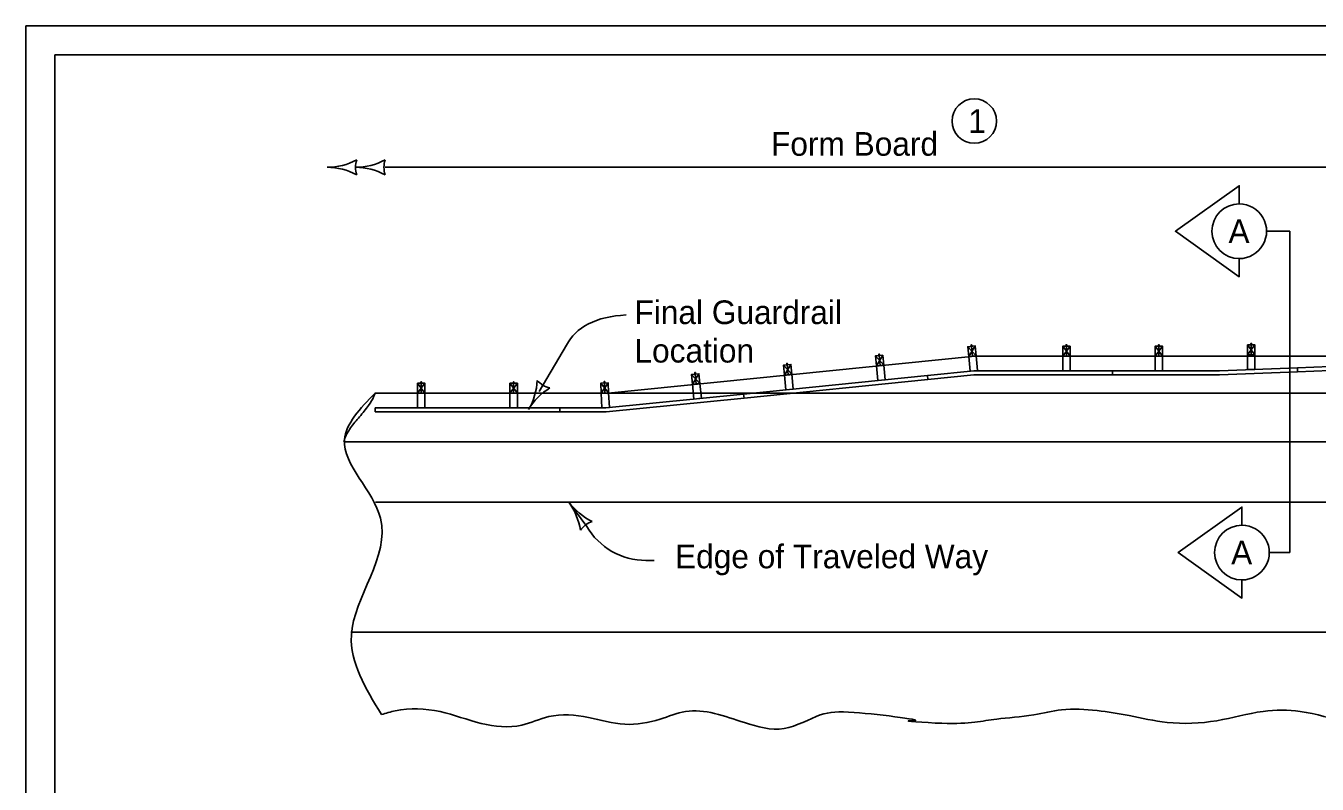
# Model space of a CAD drawing. Extents: x 10133 to 81668, y 5848 to 11018.
# Drawn here: x 10133 to 11006, y 9431 to 9944 of the extents above; entities that cross this region are included whole.
import ezdxf

# ---------------------------------------------------------------- set-up
doc = ezdxf.new("R2010")
doc.units = 0
for name, color, linetype in [('dsnStdLabel', 7, 'Continuous'), ('dsnStdLineWork', 7, 'Continuous'), ('dsnStdNote', 7, 'Continuous'), ('dsnStdPattern', 7, 'Continuous'), ('dsnStdSection', 7, 'Continuous'), ('dsnStdShading', 7, 'Continuous'), ('SheetBorder', 7, 'Continuous'), ('ShtPlotShape', 7, 'Continuous'), ('ShtPlotShapeBatchPrint', 7, 'Continuous')]:
    doc.layers.add(name, color=color, linetype=linetype)

msp = doc.modelspace()

# ---------------------------------------------------------------- linework, layer by layer
at = {"layer": 'dsnStdLabel'}
msp.add_circle((10773.85, 9879.62), 15, dxfattribs=at)
at = {"layer": 'dsnStdLineWork'}
for p, q in [((11403.96, 9729.27), (10992.39, 9712.81)), ((10526.39, 9695.63), (10774.18, 9720.71)), ((11022.02, 9720.71), (10774.18, 9720.71)), ((11404.06, 9726.57), (10992.39, 9710.1)), ((10992.39, 9712.81), (10939.63, 9710.7)), ((10992.5, 9710.11), (10939.65, 9707.99)), ((10992.39, 9712.81), (10992.5, 9710.11)), ((10992.39, 9712.81), (10992.5, 9710.11)), ((10368.64, 9695.63), (10526.39, 9695.63)), ((10368.64, 9695.63), (11500.75, 9695.63)), ((10347.65, 9662.65), (11995.12, 9662.65)), ((11500.75, 9662.65), (10347.65, 9662.65)), ((10368.86, 9622), (11982.65, 9622))]:
    msp.add_line(p, q, dxfattribs=at)
for points in [[(10368.64, 9695.63), (10347.99, 9664.08), (10372.36, 9611), (10352.66, 9531.9), (10372.93, 9478.29)], [(10347.65, 9662.65), (10347.99, 9664.08), (10349.68, 9668.15), (10352.09, 9672.07), (10358.15, 9679.69), (10364.3, 9687.38), (10367.83, 9693.49), (10368.64, 9695.63)], [(10372.93, 9478.29), (10382.36, 9480.86), (10412.58, 9480.29), (10440.52, 9472.31), (10467.89, 9471.16), (10486.14, 9476.87), (10512.94, 9476.3), (10537.46, 9471.74), (10561.41, 9475.16), (10578.52, 9480.29), (10618.43, 9472.88), (10645.23, 9468.88), (10669.75, 9478.01), (10692.56, 9479.72), (10731.34, 9474.02), (10730.77, 9474.02), (10751.92, 9472.41), (10788.99, 9475.27), (10814.08, 9478.12), (10832.9, 9481.54), (10856.85, 9480.97), (10878.51, 9477.55), (10904.17, 9472.98), (10937.82, 9474.13), (10969.18, 9480.4), (10994.27, 9480.4), (11026.2, 9472.98), (11055.29, 9470.13), (11088.93, 9476.98), (11121.43, 9480.4), (11155.65, 9473.55), (11181.31, 9470.7), (11203.54, 9474.13), (11231.49, 9489.53), (11241.75, 9491.81), (11266.27, 9494.09), (11296.93, 9494.66), (11318.03, 9494.66), (11371.34, 9485.38)]]:
    msp.add_spline(points, degree=3, dxfattribs=at)
at = {"layer": 'dsnStdNote'}
for p, q in [((10774.47, 9727.54), (10770.15, 9720.41)), ((10771.88, 9728.26), (10771.87, 9728.33)), ((10833.64, 9727.37), (10838.64, 9720.71)), ((10838.64, 9727.37), (10833.64, 9720.71)), ((10836.14, 9728.35), (10836.14, 9728.42)), ((10836.14, 9720.71), (10836.14, 9727.37)), ((10896.14, 9727.37), (10901.14, 9720.71)), ((10901.14, 9727.37), (10896.14, 9720.71)), ((10898.64, 9728.35), (10898.64, 9728.42)), ((10898.64, 9720.71), (10898.64, 9727.37)), ((10958.64, 9728.24), (10963.64, 9721.57)), ((10963.64, 9728.24), (10958.64, 9721.57)), ((10961.14, 9729.21), (10961.14, 9729.28)), ((10961.14, 9721.57), (10961.14, 9728.24)), ((10707.03, 9720.76), (10712.67, 9714.63)), ((10712, 9721.26), (10707.69, 9714.13)), ((10709.42, 9721.98), (10709.41, 9722.05)), ((10710.18, 9714.38), (10709.51, 9721.01)), ((10769.49, 9727.04), (10775.13, 9720.91)), ((10770.15, 9720.41), (10775.13, 9720.91)), ((10772.64, 9720.66), (10770.15, 9720.41)), ((10772.64, 9720.66), (10770.15, 9720.41)), ((10771.15, 9710.45), (10770.15, 9720.41)), ((10772.64, 9720.66), (10771.98, 9727.29)), ((10775.13, 9720.91), (10776.13, 9710.95)), ((10833.64, 9720.71), (10838.64, 9720.71)), ((10833.64, 9710.7), (10833.64, 9720.71)), ((10838.64, 9720.71), (10838.64, 9710.7)), ((10896.14, 9720.71), (10901.14, 9720.71)), ((10896.14, 9710.7), (10896.14, 9720.71)), ((10901.14, 9720.71), (10901.14, 9710.7)), ((10958.64, 9721.57), (10963.64, 9721.57)), ((10958.64, 9711.56), (10958.64, 9721.57)), ((10963.64, 9721.57), (10963.64, 9711.56)), ((10644.84, 9714.51), (10650.48, 9708.38)), ((10649.81, 9715.01), (10645.51, 9707.88)), ((10647.23, 9715.73), (10647.22, 9715.8)), ((10647.99, 9708.13), (10647.33, 9714.76)), ((10707.69, 9714.13), (10712.67, 9714.63)), ((10708.69, 9704.17), (10707.69, 9714.13)), ((10712.67, 9714.63), (10713.67, 9704.67)), ((10773.64, 9710.7), (10742.28, 9707.55)), ((10776.13, 9710.95), (10771.15, 9710.45)), ((10773.64, 9710.7), (10867.39, 9710.7)), ((10838.64, 9710.7), (10833.64, 9710.7)), ((10867.39, 9707.99), (10867.39, 9710.7)), ((10867.39, 9710.7), (10939.63, 9710.7)), ((10867.39, 9707.99), (10867.39, 9710.7)), ((10901.14, 9710.7), (10896.14, 9710.7)), ((10963.64, 9711.56), (10958.64, 9711.56)), ((10397.39, 9702.3), (10402.39, 9695.63)), ((10402.39, 9702.3), (10397.39, 9695.63)), ((10399.89, 9703.27), (10399.89, 9703.34)), ((10399.89, 9695.63), (10399.89, 9702.3)), ((10459.89, 9702.3), (10464.89, 9695.63)), ((10464.89, 9702.3), (10459.89, 9695.63)), ((10462.39, 9703.27), (10462.39, 9703.34)), ((10462.39, 9695.63), (10462.39, 9702.3)), ((10521.28, 9702.36), (10526.61, 9695.92)), ((10526.28, 9702.61), (10521.62, 9695.67)), ((10523.73, 9703.46), (10523.73, 9703.53)), ((10524.11, 9695.8), (10523.78, 9702.49)), ((10582.66, 9708.3), (10588.3, 9702.13)), ((10587.64, 9708.8), (10583.33, 9701.63)), ((10583.33, 9701.63), (10588.3, 9702.13)), ((10584.32, 9691.63), (10583.33, 9701.63)), ((10585.05, 9709.52), (10585.05, 9709.59)), ((10585.81, 9701.88), (10585.15, 9708.55)), ((10588.3, 9702.13), (10589.3, 9692.13)), ((10617.9, 9695.05), (10742.28, 9707.55)), ((10618.17, 9692.35), (10742.55, 9704.85)), ((10645.51, 9707.88), (10650.49, 9708.38)), ((10646.51, 9697.92), (10645.51, 9707.88)), ((10650.49, 9708.38), (10651.49, 9698.42)), ((10713.67, 9704.67), (10708.69, 9704.17)), ((10742.55, 9704.85), (10742.28, 9707.55)), ((10742.55, 9704.87), (10742.28, 9707.55)), ((10773.64, 9707.99), (10742.55, 9704.87)), ((10773.64, 9707.99), (10867.39, 9707.99)), ((10867.39, 9707.99), (10939.65, 9707.99)), ((10397.39, 9695.63), (10402.4, 9695.63)), ((10397.39, 9685.63), (10397.39, 9695.63)), ((10402.4, 9695.63), (10402.4, 9685.63)), ((10459.89, 9695.63), (10464.9, 9695.63)), ((10459.89, 9685.63), (10459.89, 9695.63)), ((10464.9, 9695.63), (10464.9, 9685.63)), ((10521.62, 9695.67), (10526.61, 9695.92)), ((10522.11, 9685.63), (10521.62, 9695.67)), ((10524.62, 9685.63), (10617.9, 9695.05)), ((10526.61, 9695.92), (10527.11, 9685.88)), ((10618.17, 9692.34), (10617.9, 9695.05)), ((10618.17, 9692.35), (10617.9, 9695.05)), ((10651.49, 9698.42), (10646.51, 9697.92)), ((10368.64, 9685.63), (10493.64, 9685.63)), ((10368.64, 9682.92), (10368.64, 9685.63)), ((10402.4, 9685.63), (10397.39, 9685.63)), ((10464.9, 9685.63), (10459.89, 9685.63)), ((10493.64, 9685.63), (10524.62, 9685.63)), ((10493.64, 9682.92), (10493.64, 9685.63)), ((10527.11, 9685.88), (10522.11, 9685.63)), ((10524.89, 9682.92), (10618.17, 9692.34)), ((10589.3, 9692.13), (10584.32, 9691.63)), ((10368.64, 9682.92), (10493.64, 9682.92)), ((10493.64, 9682.92), (10524.89, 9682.92))]:
    msp.add_line(p, q, dxfattribs=at)
for points in [[(10770.15, 9720.41), (10775.13, 9720.91), (10774.47, 9727.54), (10769.49, 9727.04)], [(10833.64, 9720.71), (10838.64, 9720.71), (10838.64, 9727.37), (10833.64, 9727.37)], [(10896.14, 9720.71), (10901.14, 9720.71), (10901.14, 9727.37), (10896.14, 9727.37)], [(10958.64, 9721.57), (10963.64, 9721.57), (10963.64, 9728.24), (10958.64, 9728.24)], [(10707.69, 9714.13), (10712.67, 9714.63), (10712, 9721.26), (10707.03, 9720.76)], [(10645.51, 9707.88), (10650.48, 9708.38), (10649.81, 9715.01), (10644.84, 9714.51)], [(10397.39, 9695.63), (10402.39, 9695.63), (10402.39, 9702.3), (10397.39, 9702.3)], [(10459.89, 9695.63), (10464.89, 9695.63), (10464.89, 9702.3), (10459.89, 9702.3)], [(10521.62, 9695.67), (10526.61, 9695.92), (10526.28, 9702.61), (10521.28, 9702.36)], [(10583.33, 9701.63), (10588.3, 9702.13), (10587.64, 9708.8), (10582.66, 9708.3)]]:
    msp.add_lwpolyline(points, close=True, dxfattribs=at)
for points in [[(10771.65, 9727.26), (10771.6, 9727.69), (10772.27, 9727.75), (10772.31, 9727.32)], [(10771.74, 9727.7), (10771.69, 9728.24), (10772.08, 9728.28), (10772.13, 9727.74)], [(10835.8, 9727.37), (10835.8, 9727.81), (10836.47, 9727.81), (10836.47, 9727.37)], [(10835.94, 9727.81), (10835.94, 9728.35), (10836.33, 9728.35), (10836.33, 9727.81)], [(10898.31, 9727.37), (10898.31, 9727.81), (10898.97, 9727.81), (10898.97, 9727.37)], [(10898.45, 9727.81), (10898.45, 9728.35), (10898.83, 9728.35), (10898.83, 9727.81)], [(10960.81, 9728.24), (10960.81, 9728.67), (10961.47, 9728.67), (10961.47, 9728.24)], [(10960.95, 9728.67), (10960.95, 9729.21), (10961.33, 9729.21), (10961.33, 9728.67)], [(10709.18, 9720.98), (10709.14, 9721.41), (10709.8, 9721.48), (10709.85, 9721.05)], [(10709.28, 9721.42), (10709.22, 9721.96), (10709.61, 9722), (10709.66, 9721.46)], [(10647, 9714.73), (10646.95, 9715.16), (10647.62, 9715.23), (10647.66, 9714.8)], [(10647.09, 9715.17), (10647.04, 9715.71), (10647.42, 9715.75), (10647.48, 9715.21)], [(10399.56, 9702.3), (10399.56, 9702.73), (10400.23, 9702.73), (10400.23, 9702.3)], [(10399.7, 9702.73), (10399.7, 9703.27), (10400.09, 9703.27), (10400.09, 9702.73)], [(10462.06, 9702.3), (10462.06, 9702.73), (10462.73, 9702.73), (10462.73, 9702.3)], [(10462.2, 9702.73), (10462.2, 9703.27), (10462.59, 9703.27), (10462.59, 9702.73)], [(10523.45, 9702.47), (10523.43, 9702.9), (10524.09, 9702.94), (10524.11, 9702.51)], [(10523.57, 9702.91), (10523.54, 9703.45), (10523.93, 9703.47), (10523.95, 9702.93)], [(10584.82, 9708.52), (10584.78, 9708.95), (10585.44, 9709.01), (10585.48, 9708.58)], [(10584.91, 9708.96), (10584.86, 9709.5), (10585.25, 9709.54), (10585.3, 9709)], [(10524.11, 9695.8), (10521.62, 9695.67), (10521.62, 9695.67)]]:
    msp.add_lwpolyline(points, dxfattribs=at)
at = {"layer": 'dsnStdPattern'}
for p, q in [((10987.26, 9805.1), (10971.49, 9805.1)), ((10987.26, 9805.1), (10971.49, 9805.1)), ((10987.26, 9587.81), (10987.26, 9805.1)), ((10987.26, 9587.81), (10987.26, 9805.1)), ((10987.26, 9587.81), (10973.31, 9587.81)), ((10987.26, 9587.81), (10973.31, 9587.81))]:
    msp.add_line(p, q, dxfattribs=at)
for points in [[(10953, 9823.58), (10953, 9835.91), (10909.87, 9805.1), (10953, 9774.29), (10953, 9786.61)], [(10954.82, 9606.3), (10954.82, 9618.62), (10911.69, 9587.81), (10954.82, 9557), (10954.82, 9569.33)]]:
    msp.add_lwpolyline(points, dxfattribs=at)
for centre, start, end in [((10953, 9805.1), 90.00083, 269.99917), ((10953, 9805.1), 269.99917, 90.00083), ((10954.82, 9587.81), 90.00083, 269.99917), ((10954.82, 9587.81), 269.99917, 90.00083)]:
    msp.add_arc(centre, 18.49, start, end, dxfattribs=at)
at = {"layer": 'dsnStdSection'}
for p, q in [((10498.16, 9728.01), (10479.61, 9696.66)), ((10498.16, 9728.01), (10479.61, 9696.66)), ((10511.77, 9605.55), (10499.66, 9622)), ((10511.77, 9605.55), (10499.66, 9622)), ((10551.86, 9582.48), (10557.31, 9582.48)), ((10551.86, 9582.48), (10557.31, 9582.48))]:
    msp.add_line(p, q, dxfattribs=at)
for centre, radius, start, end in [((10435.84, 9706.16), 42.5, 329.37973, 357.45222), ((10435.84, 9706.16), 42.5, 329.37973, 357.45222), ((10490.57, 9715.18), 16.42, 221.64638, 257.11308), ((10490.57, 9715.18), 16.42, 221.64638, 257.11308), ((10508.99, 9662.87), 42.5, 121.30724, 149.37973), ((10508.99, 9662.87), 42.5, 121.30724, 149.37973), ((10533.88, 9647.21), 42.5, 216.37256, 244.44505), ((10465.44, 9596.8), 42.5, 8.30007, 36.37256), ((10533.88, 9647.21), 42.5, 216.37256, 244.44505), ((10465.44, 9596.8), 42.5, 8.30007, 36.37256), ((10520.79, 9593.31), 16.42, 108.63921, 144.10591), ((10520.79, 9593.31), 16.42, 108.63921, 144.10591), ((10551.92, 9628.94), 46.46, 210.22743, 270), ((10551.92, 9628.94), 46.46, 210.22743, 270)]:
    msp.add_arc(centre, radius, start, end, dxfattribs=at)
msp.add_ellipse((10579.25, 9688.96), major_axis=(-81.09, 39.04), ratio=0.555556, start_param=5.482641, end_param=6.283185, dxfattribs=at)
msp.add_ellipse((10579.25, 9688.96), major_axis=(-81.09, 39.04), ratio=0.555556, start_param=5.482641, end_param=6.283185, dxfattribs=at)
at = {"layer": 'dsnStdShading'}
for p, q in [((10774.18, 9720.71), (10526.39, 9695.63)), ((11025.35, 9720.71), (10774.18, 9720.71)), ((10526.39, 9695.63), (11500.75, 9695.63)), ((11558.3, 9695.63), (10526.39, 9695.63)), ((10352.26, 9534.09), (11994.29, 9534.09))]:
    msp.add_line(p, q, dxfattribs=at)
at = {"layer": 'SheetBorder'}
msp.add_lwpolyline([(10132.52, 9944.02), (13267.53, 9944.02), (13267.53, 7924.02), (10132.52, 7924.02)], close=True, dxfattribs=at)
at = {"layer": 'ShtPlotShape'}
msp.add_line((10375.45, 9848.49), (11397.86, 9848.49), dxfattribs=at)
msp.add_line((10375.45, 9848.49), (11397.86, 9848.49), dxfattribs=at)
for centre, radius, start, end in [((10336.23, 9890.84), 42.5, 270, 298.07249), ((10336.23, 9890.84), 42.5, 270, 298.07249), ((10355.45, 9890.84), 42.5, 270, 298.07249), ((10371.87, 9848.34), 16.42, 162.26665, 197.73335), ((10355.45, 9890.84), 42.5, 270, 298.07249), ((10371.87, 9848.34), 16.42, 162.26665, 197.73335), ((10391.09, 9848.34), 16.42, 162.26665, 197.73335), ((10391.09, 9848.34), 16.42, 162.26665, 197.73335), ((10336.23, 9805.84), 42.5, 61.92751, 90), ((10336.23, 9805.84), 42.5, 61.92751, 90), ((10355.45, 9805.84), 42.5, 61.92751, 90), ((10355.45, 9805.84), 42.5, 61.92751, 90)]:
    msp.add_arc(centre, radius, start, end, dxfattribs=at)
at = {"layer": 'ShtPlotShapeBatchPrint'}
for q in [(10152.18, 8314.36), (13247.87, 9924.36)]:
    msp.add_line((10152.18, 9924.36), q, dxfattribs=at)

# ---------------------------------------------------------------- texts
at = {"layer": 'dsnStdLabel'}
msp.add_text('1', height=16, dxfattribs=at).set_placement((10769.77, 9871.62))
at = {"layer": 'dsnStdPattern'}
for p in [(10945.73, 9797.1), (10947.55, 9579.81)]:
    msp.add_text('A', height=16, dxfattribs=at).set_placement(p)
at = {"layer": 'dsnStdSection'}
for s, p in [('Final Guardrail ', (10544.06, 9742.33)), ('Final Guardrail ', (10544.06, 9742.33)), ('Location', (10544.06, 9716.33)), ('Location', (10544.06, 9716.33)), ('Edge of Traveled Way', (10571.5, 9577.21)), ('Edge of Traveled Way', (10571.5, 9577.21))]:
    msp.add_text(s, height=16, dxfattribs=at).set_placement(p)
at = {"layer": 'ShtPlotShape'}
msp.add_text('Form Board', height=16, dxfattribs=at).set_placement((10636.4, 9856.18))
msp.add_text('Form Board', height=16, dxfattribs=at).set_placement((10636.4, 9856.18))

doc.saveas('drawing.dxf')
